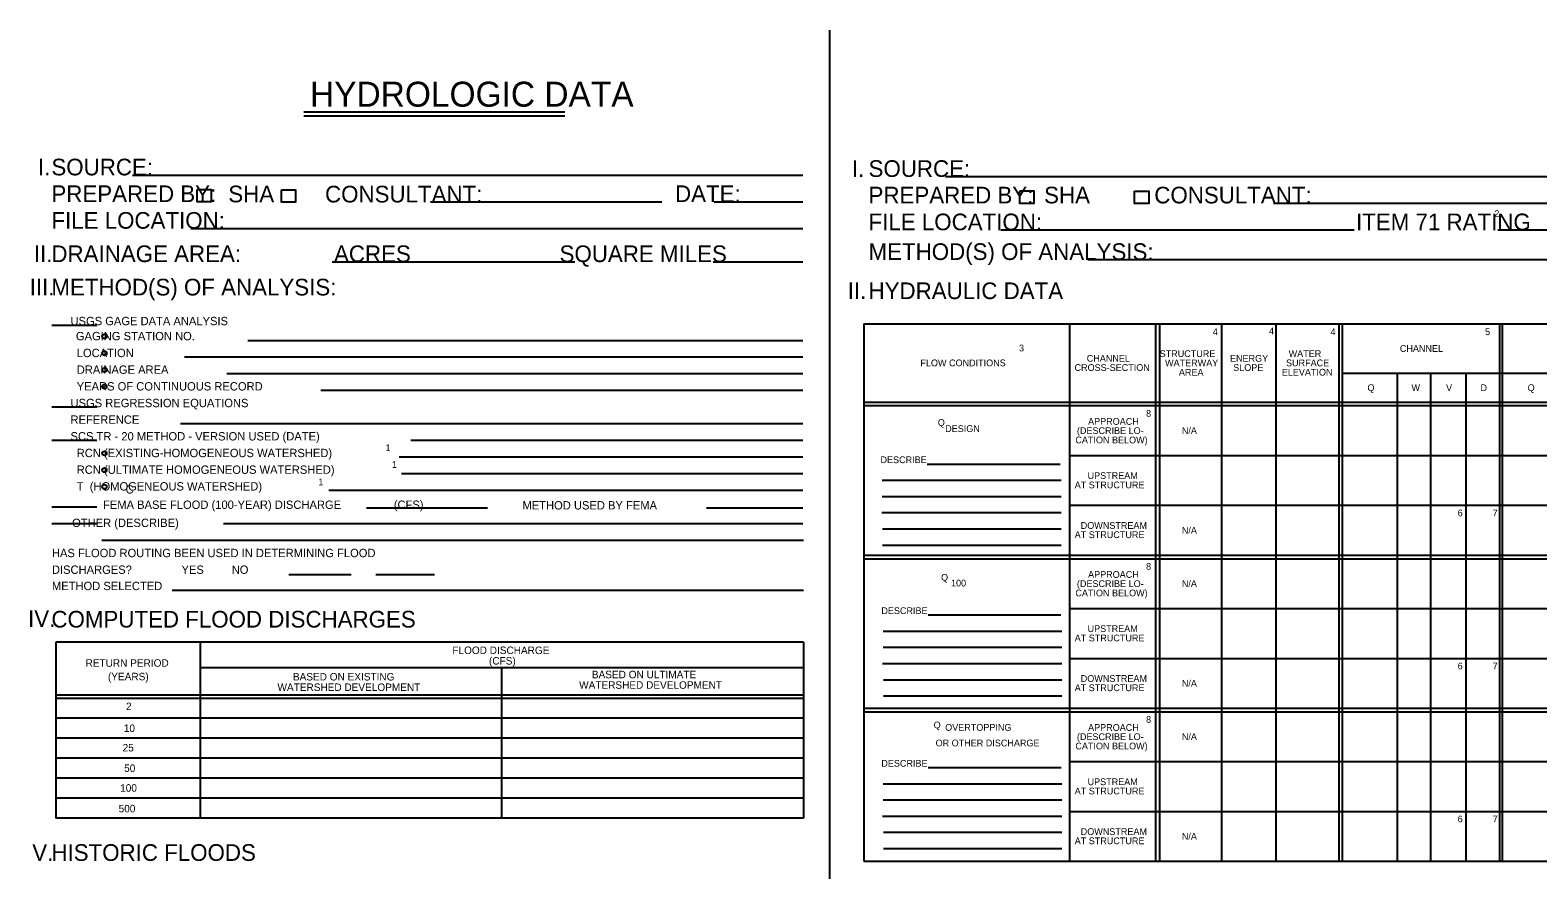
# Model space of a CAD drawing. Extents: x 2.9 to 32.9, y 0.8 to 21.2.
# Drawn here: x 2.91 to 20.69, y 11.27 to 21.19 of the extents above; entities that cross this region are included whole.
import ezdxf

# ---------------------------------------------------------------- set-up
doc = ezdxf.new("R2010")
doc.units = 0
doc.layers.add('G-ANNO-NOTE', color=7, linetype='Continuous')

msp = doc.modelspace()

# ---------------------------------------------------------------- linework, layer by layer
at = {"layer": 'G-ANNO-NOTE'}
for p, q in [((12.339, 21.185), (12.339, 0.75)), ((6.134, 20.222), (9.215, 20.222)), ((6.134, 20.173), (9.215, 20.173)), ((12.022, 19.47), (4.114, 19.47)), ((21.631, 19.452), (13.706, 19.452)), ((10.36, 19.155), (7.632, 19.155)), ((12.022, 19.155), (10.978, 19.155)), ((22.558, 19.137), (17.576, 19.137)), ((19.022, 19.137), (18.992, 19.137)), ((12.022, 18.84), (4.802, 18.84)), ((18.525, 18.822), (14.359, 18.822)), ((24.999, 18.822), (20.223, 18.822)), ((9.333, 18.446), (6.47, 18.446)), ((12.022, 18.446), (10.965, 18.446)), ((24.999, 18.471), (15.386, 18.471)), ((19.647, 18.471), (18.753, 18.471)), ((19.58, 18.471), (19.462, 18.471)), ((21.708, 18.471), (20.342, 18.471)), ((21.708, 18.471), (20.348, 18.471)), ((3.694, 17.697), (3.164, 17.697)), ((12.741, 17.718), (24.999, 17.718)), ((12.741, 17.718), (12.741, 11.372)), ((15.167, 17.718), (15.167, 11.372)), ((16.185, 17.718), (16.185, 11.372)), ((16.23, 17.718), (16.23, 11.372)), ((16.963, 17.718), (16.963, 11.372)), ((17.601, 17.718), (17.601, 11.372)), ((18.345, 17.718), (18.345, 11.372)), ((18.384, 17.718), (18.384, 11.372)), ((20.24, 17.718), (20.24, 11.372)), ((20.274, 17.718), (20.274, 11.372)), ((12.022, 17.517), (5.477, 17.517)), ((12.022, 17.324), (4.727, 17.324)), ((12.022, 17.127), (5.226, 17.127)), ((18.384, 17.133), (24.999, 17.133)), ((19.036, 17.133), (19.036, 11.372)), ((19.429, 17.133), (19.429, 11.372)), ((19.844, 17.133), (19.844, 11.372)), ((12.022, 16.93), (6.338, 16.93)), ((3.694, 16.733), (3.164, 16.733)), ((12.741, 16.793), (24.999, 16.793)), ((12.741, 16.751), (24.999, 16.751)), ((12.022, 16.537), (4.682, 16.537)), ((3.694, 16.34), (3.164, 16.34)), ((12.022, 16.34), (7.397, 16.34)), ((12.022, 16.143), (7.261, 16.143)), ((14.991, 16.058), (13.489, 16.058)), ((15.058, 16.058), (13.526, 16.058)), ((15.167, 16.162), (24.999, 16.162)), ((16.231, 16.15), (16.231, 16.15)), ((12.022, 15.946), (7.289, 15.946)), ((15.069, 15.867), (12.959, 15.867)), ((12.022, 15.749), (6.429, 15.749)), ((15.069, 15.675), (12.959, 15.675)), ((3.694, 15.552), (3.164, 15.552)), ((8.301, 15.539), (6.876, 15.539)), ((12.022, 15.539), (10.888, 15.539)), ((15.069, 15.484), (12.954, 15.484)), ((15.167, 15.577), (24.999, 15.577)), ((3.694, 15.355), (3.164, 15.355)), ((12.022, 15.355), (5.187, 15.355)), ((12.031, 15.159), (3.754, 15.159)), ((12.013, 15.159), (6.462, 15.159)), ((15.069, 15.293), (12.963, 15.293)), ((12.741, 14.986), (24.999, 14.986)), ((12.741, 14.944), (24.999, 14.944)), ((15.069, 15.101), (12.963, 15.101)), ((6.696, 14.755), (5.957, 14.755)), ((7.677, 14.755), (6.984, 14.755)), ((12.031, 14.57), (4.581, 14.57)), ((15.001, 14.276), (13.5, 14.276)), ((13.538, 14.276), (13.536, 14.276)), ((15.068, 14.276), (13.562, 14.276)), ((15.167, 14.355), (24.999, 14.355)), ((15.079, 14.085), (12.969, 14.085)), ((12.031, 13.959), (3.212, 13.959)), ((3.212, 13.959), (3.212, 11.881)), ((4.913, 13.959), (4.913, 13.534)), ((12.031, 13.959), (12.031, 11.881)), ((15.079, 13.894), (12.969, 13.894)), ((15.079, 13.702), (12.964, 13.702)), ((15.167, 13.767), (24.999, 13.767)), ((8.472, 13.654), (4.913, 13.654)), ((4.913, 13.534), (4.913, 11.881)), ((12.031, 13.654), (8.472, 13.654)), ((8.472, 11.881), (8.472, 13.651)), ((15.079, 13.511), (12.973, 13.511)), ((12.031, 13.333), (3.212, 13.333)), ((12.031, 13.292), (3.212, 13.292)), ((12.741, 13.179), (24.999, 13.179)), ((15.079, 13.319), (12.973, 13.319)), ((12.031, 13.062), (3.212, 13.062)), ((12.741, 13.136), (24.999, 13.136)), ((12.031, 12.826), (3.212, 12.826)), ((12.031, 12.59), (3.212, 12.59)), ((15.07, 12.474), (13.5, 12.474)), ((14.99, 12.474), (13.536, 12.474)), ((15.167, 12.548), (24.999, 12.548)), ((12.031, 12.354), (3.212, 12.354)), ((15.079, 12.283), (12.969, 12.283)), ((12.031, 12.117), (3.212, 12.117)), ((15.079, 12.092), (12.969, 12.092)), ((15.167, 11.96), (24.999, 11.96)), ((12.031, 11.881), (3.212, 11.881)), ((12.031, 11.881), (3.212, 11.881)), ((15.079, 11.9), (12.964, 11.9)), ((15.079, 11.709), (12.973, 11.709)), ((15.079, 11.518), (12.973, 11.518)), ((12.741, 11.372), (24.999, 11.372))]:
    msp.add_line(p, q, dxfattribs=at)
for points in [[(4.877, 19.302), (5.044, 19.302), (5.044, 19.156), (4.877, 19.156)], [(5.871, 19.3), (6.038, 19.3), (6.038, 19.154), (5.871, 19.154)], [(14.581, 19.286), (14.747, 19.286), (14.747, 19.139), (14.581, 19.139)], [(15.937, 19.284), (16.104, 19.284), (16.104, 19.138), (15.937, 19.138)]]:
    msp.add_lwpolyline(points, close=True, dxfattribs=at)
for centre in [(3.784, 17.568), (3.784, 17.369), (3.784, 17.172), (3.784, 16.976), (3.784, 16.188), (3.784, 15.991), (3.784, 15.794)]:
    msp.add_circle(centre, 0.0255, dxfattribs=at)

# ---------------------------------------------------------------- texts
for s, height, p in [('HYDROLOGIC DATA', 0.29528, (6.209, 20.281)), ('I.  ', 0.1968, (3, 19.47)), ('SOURCE:', 0.1968, (3.158, 19.47)), ('I. ', 0.1968, (12.601, 19.452)), ('SOURCE:', 0.1968, (12.798, 19.452)), ('PREPARED BY:', 0.19677, (3.158, 19.155)), ('SHA', 0.1968, (5.245, 19.152)), ('CONSULTANT:', 0.19677, (6.386, 19.15)), ('DATE:', 0.1968, (10.515, 19.155)), ('PREPARED BY:', 0.19677, (12.798, 19.139)), ('SHA', 0.1968, (14.869, 19.139)), ('CONSULTANT:', 0.19677, (16.169, 19.139)), ('FILE LOCATION:', 0.19677, (3.158, 18.84)), ('2', 0.0797, (20.18, 18.979)), ('FILE LOCATION:', 0.19677, (12.798, 18.822)), ('ITEM 71 RATING', 0.19677, (18.549, 18.822)), ('METHOD(S) OF ANALYSIS:', 0.19677, (12.798, 18.471)), ('II.  ', 0.1968, (2.951, 18.446)), ('DRAINAGE AREA:               ACRES                        SQUARE MILES', 0.19677, (3.158, 18.446)), ('III.  ', 0.1968, (2.902, 18.052)), ('METHOD(S) OF ANALYSIS:', 0.19677, (3.158, 18.052)), ('II. ', 0.1968, (12.552, 18.012)), ('HYDRAULIC DATA ', 0.19677, (12.798, 18.009)), ('      USGS GAGE DATA ANALYSIS', 0.09843, (3.164, 17.701)), ('        GAGING STATION NO.', 0.09843, (3.154, 17.523)), ('4', 0.0797, (16.859, 17.584)), ('4', 0.0797, (17.522, 17.592)), ('4', 0.0797, (18.248, 17.584)), ('5', 0.0797, (20.071, 17.584)), ('3', 0.0797, (14.573, 17.392)), ('CHANNEL', 0.0797, (19.066, 17.386)), ('        LOCATION', 0.09843, (3.164, 17.324)), ('   FLOW CONDITIONS', 0.07969, (13.321, 17.216)), ('  CHANNEL ', 0.0797, (15.313, 17.27)), ('STRUCTURE ', 0.0797, (16.232, 17.325)), ('WATERWAY', 0.0797, (16.296, 17.216)), ('ENERGY ', 0.0797, (17.062, 17.27)), ('SURFACE', 0.0797, (17.723, 17.216)), ('WATER ', 0.0797, (17.754, 17.325)), ('        DRAINAGE AREA', 0.09843, (3.164, 17.127)), ('CROSS-SECTION', 0.07969, (15.228, 17.161)), ('AREA', 0.0797, (16.459, 17.106)), ('SLOPE', 0.0797, (17.1, 17.161)), ('ELEVATION', 0.0797, (17.673, 17.106)), ('        YEARS OF CONTINUOUS RECORD', 0.09843, (3.164, 16.93)), ('Q', 0.0797, (18.684, 16.923)), ('W', 0.0797, (19.203, 16.923)), ('V', 0.0797, (19.611, 16.923)), ('D', 0.0797, (20.017, 16.923)), ('Q', 0.0797, (20.574, 16.923)), ('      USGS REGRESSION EQUATIONS', 0.09843, (3.164, 16.733)), ('      REFERENCE', 0.09843, (3.164, 16.537)), ('Q', 0.0797, (13.615, 16.512)), ('APPROACH', 0.0797, (15.388, 16.525)), ('8', 0.0797, (16.072, 16.62)), ('      SCS TR - 20 METHOD - VERSION USED (DATE)', 0.09843, (3.164, 16.34)), ('DESIGN  ', 0.0797, (13.702, 16.44)), ('CATION BELOW)', 0.07969, (15.238, 16.306)), ('(DESCRIBE LO-', 0.07969, (15.256, 16.416)), ('N/A', 0.0797, (16.494, 16.417)), ('        RCN (EXISTING-HOMOGENEOUS WATERSHED)', 0.09843, (3.164, 16.143)), ('1', 0.0797, (7.1, 16.216)), ('        RCN (ULTIMATE HOMOGENEOUS WATERSHED)', 0.09843, (3.164, 15.946)), ('1', 0.0797, (7.175, 16.016)), ('DESCRIBE', 0.0797, (12.939, 16.072)), ('        T  (HOMOGENEOUS WATERSHED)', 0.09843, (3.164, 15.749)), ('1', 0.0797, (6.307, 15.81)), ('AT STRUCTURE', 0.07969, (15.23, 15.775)), ('UPSTREAM', 0.0797, (15.382, 15.885)), ('C', 0.0984, (4.033, 15.713)), ('FEMA BASE FLOOD (100-YEAR) DISCHARGE                 (CFS)', 0.09843, (3.767, 15.532)), ('      METHOD USED BY FEMA', 0.09843, (8.496, 15.525)), ('6', 0.0797, (19.748, 15.444)), ('7', 0.0797, (20.161, 15.445)), ('      OTHER (DESCRIBE)', 0.09843, (3.183, 15.318)), ('DOWNSTREAM', 0.0797, (15.301, 15.296)), ('N/A', 0.0797, (16.494, 15.24)), ('AT STRUCTURE', 0.07969, (15.23, 15.187)), ('HAS FLOOD ROUTING BEEN USED IN DETERMINING FLOOD ', 0.09843, (3.164, 14.962)), ('DISCHARGES?                YES         NO ', 0.09843, (3.164, 14.765)), ('Q  ', 0.0797, (13.654, 14.684)), ('APPROACH', 0.0797, (15.388, 14.718)), ('8', 0.0797, (16.072, 14.813)), ('METHOD SELECTED', 0.09843, (3.164, 14.573)), ('100  ', 0.0797, (13.771, 14.616)), ('(DESCRIBE LO-', 0.07969, (15.256, 14.609)), ('N/A', 0.0797, (16.494, 14.61)), ('CATION BELOW)', 0.07969, (15.238, 14.499)), ('IV.  ', 0.1968, (2.883, 14.138)), ('COMPUTED FLOOD DISCHARGES', 0.19677, (3.158, 14.131)), ('DESCRIBE', 0.0797, (12.949, 14.29)), ('UPSTREAM', 0.0797, (15.382, 14.078)), ('FLOOD DISCHARGE', 0.08858, (7.888, 13.818)), ('AT STRUCTURE', 0.07969, (15.23, 13.968)), ('RETURN PERIOD', 0.08858, (3.561, 13.668)), ('(CFS)', 0.0886, (8.32, 13.694)), ('6', 0.0797, (19.748, 13.637)), ('7', 0.0797, (20.161, 13.638)), ('(YEARS)', 0.0886, (3.825, 13.508)), ('BASED ON EXISTING ', 0.08858, (6.007, 13.506)), ('BASED ON ULTIMATE ', 0.08858, (9.534, 13.532)), ('DOWNSTREAM', 0.0797, (15.301, 13.489)), ('WATERSHED DEVELOPMENT', 0.08858, (5.825, 13.382)), ('WATERSHED DEVELOPMENT', 0.08858, (9.384, 13.408)), ('AT STRUCTURE', 0.07969, (15.23, 13.38)), ('N/A', 0.0797, (16.494, 13.433)), ('2', 0.0886, (4.038, 13.156)), ('10', 0.0886, (4.012, 12.898)), ('Q', 0.0797, (13.566, 12.941)), ('OVERTOPPING', 0.07969, (13.702, 12.912)), ('APPROACH', 0.0797, (15.388, 12.911)), ('8', 0.0797, (16.072, 13.006)), ('OR OTHER DISCHARGE', 0.07969, (13.589, 12.728)), ('(DESCRIBE LO-', 0.07969, (15.256, 12.802)), ('N/A', 0.0797, (16.494, 12.803)), ('25', 0.0886, (3.998, 12.668)), ('CATION BELOW)', 0.07969, (15.238, 12.692)), ('50', 0.0886, (4.016, 12.426)), ('DESCRIBE', 0.0797, (12.949, 12.488)), ('100', 0.0886, (3.969, 12.193)), ('UPSTREAM', 0.0797, (15.382, 12.27)), ('AT STRUCTURE', 0.07969, (15.23, 12.161)), ('500', 0.0886, (3.951, 11.949)), ('DOWNSTREAM', 0.0797, (15.301, 11.682)), ('6', 0.0797, (19.748, 11.83)), ('7', 0.0797, (20.161, 11.831)), ('V.  ', 0.1968, (2.932, 11.376)), ('HISTORIC FLOODS', 0.19677, (3.158, 11.376)), ('AT STRUCTURE', 0.07969, (15.23, 11.573)), ('N/A', 0.0797, (16.494, 11.626))]:
    msp.add_text(s, height=height, dxfattribs=at).set_placement(p)

doc.saveas('drawing.dxf')
